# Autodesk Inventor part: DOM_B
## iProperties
Created: 2006-08
Part Number: DOM_B
Document SubType Name: Modeling
Designer: WINDGES
Material: Steel
Author: WINDGES
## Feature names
1. Extrusion1
2. Extrusion2
3. Extrusion3
4. Extrusion4
